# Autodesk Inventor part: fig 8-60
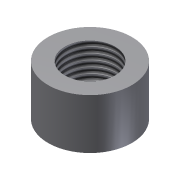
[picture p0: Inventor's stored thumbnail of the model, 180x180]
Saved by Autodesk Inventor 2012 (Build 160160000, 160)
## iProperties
Shininess: 77.0
Length Units: 11269
Angle Units: 11279
Time Units: 11290
Mass Units: 11283
Length Display Precision: 3
Angle Display Precision: 2
Compacted: True
Created: 2002-01
Part Number: fig 8-60
Document SubType Name: Modeling
Designer: ***
Density: 1 g/cm^3
Material: Default
Density: 0.0
Volumn: 0.0
Area: 0.0
PropertySet Name: Model Information
Control State: 0
Master: False
Checked Out: False
Author: ***
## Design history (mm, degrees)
sketch "Sketch1"
  geometry: C1 r 25 at (0, 0); C2 r 15 at (0, 0)
  constraints: 2 centre point, 1 coincident
  dimensions: "d0" = 50 diameter of C1; "d1" = 30 diameter of C2
extrude "Extrusion1" new body sketch "Sketch1" distance "d2" = 30; taper "d3" = 0 deg
thread "Thread5" dims "d12" = 10, "d13" = 0
body "Solid1"
